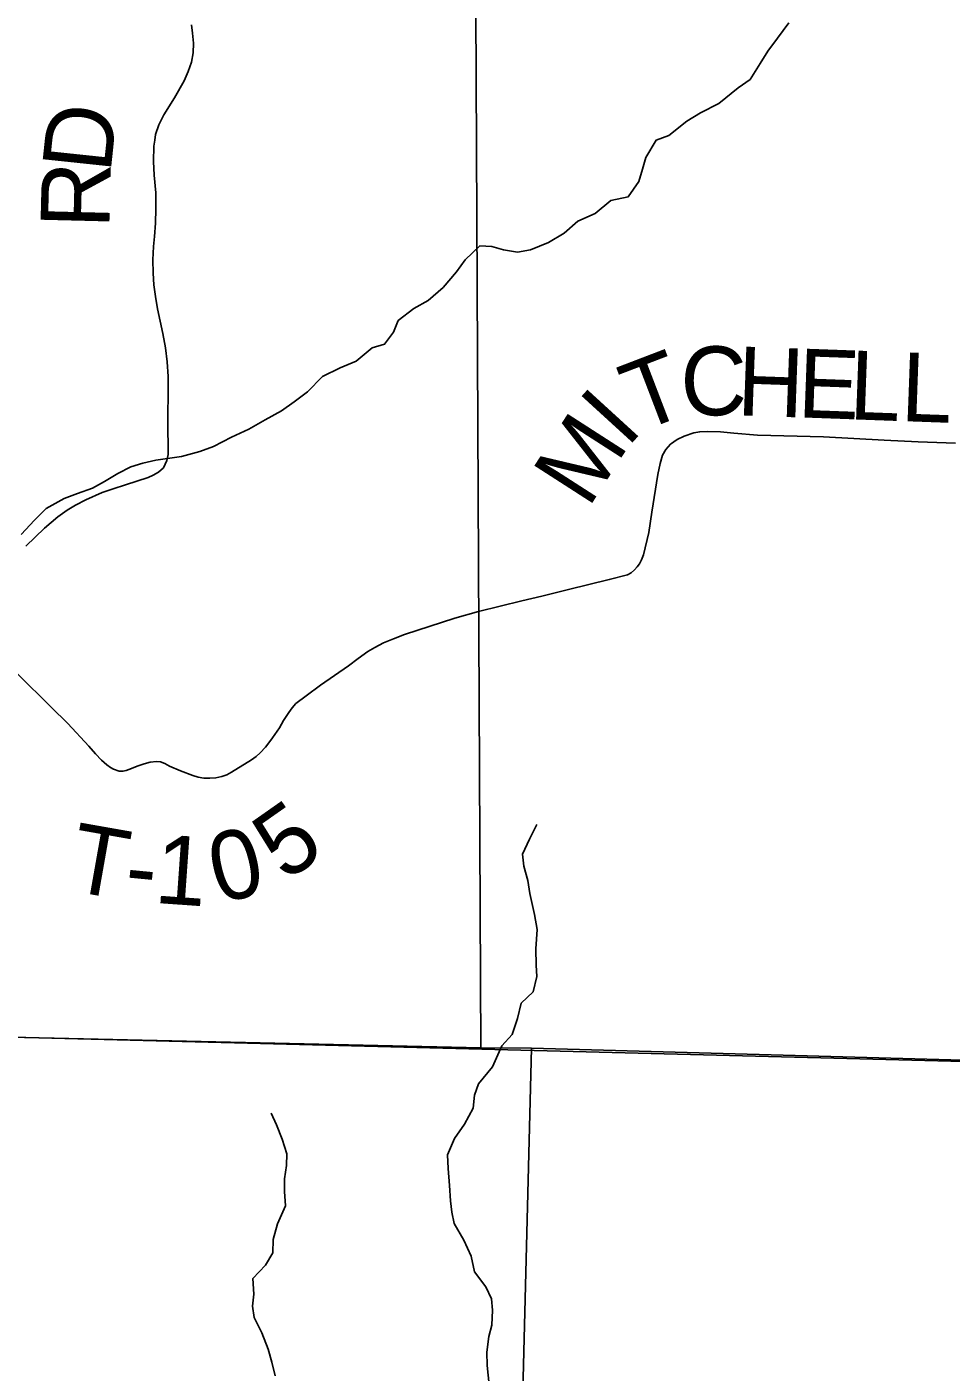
# Model space of a CAD drawing. Extents: x 0 to 34, y 0 to 22.
# Drawn here: x 5.404 to 6.166, y 15.796 to 16.906 of the extents above; entities that cross this region are included whole.
import ezdxf

# ---------------------------------------------------------------- set-up
doc = ezdxf.new("R2010")
doc.units = 0
for name, color, linetype in [('GM_X_Corporation', 7, 'Continuous'), ('GM_X_Minor_River', 7, 'Continuous'), ('GM_X_Township_Road', 7, 'Continuous'), ('GM_X_Township_Road_Text', 7, 'Continuous')]:
    doc.layers.add(name, color=color, linetype=linetype)

msp = doc.modelspace()

# ---------------------------------------------------------------- linework, layer by layer
at = {"layer": 'GM_X_Corporation'}
for points in [[(4.7905, 18.3604), (4.7823, 18.128), (4.7806, 18.0273), (4.765, 16.8754), (4.756, 16.2274), (4.759, 16.0879), (4.9206, 16.0842), (4.928, 16.0841), (4.9731, 16.0831), (4.975, 16.083), (5.0347, 16.0817), (5.0373, 16.0816), (6.4668, 16.045), (6.4721, 16.0449), (6.6873, 16.0404), (6.6909, 16.0403), (6.7034, 16.04), (6.9699, 16.0345), (6.9736, 16.0344), (7.8043, 16.0135), (7.8077, 16.0135), (8.4311, 16.0029), (8.4311, 20.028)], [(6.4668, 16.045), (5.0373, 16.0816)]]:
    msp.add_lwpolyline(points, dxfattribs=at)
for points in [[(6.7684, 17.0582), (6.7585, 16.0372), (5.82, 16.0635), (5.7783, 16.0638), (5.7733, 17.0918)], [(4.7583, 16.0869), (5.7783, 16.0638), (5.82, 16.0635), (5.7937, 15.0184), (4.7356, 15.0283), (4.7361, 15.0901)], [(5.82, 16.0635), (6.7585, 16.0372), (6.8244, 16.0368), (6.804, 15.0104), (5.7937, 15.0184)]]:
    msp.add_lwpolyline(points, close=True, dxfattribs=at)
at = {"layer": 'GM_X_Minor_River'}
for points in [[(5.399, 16.4872), (5.41, 16.499), (5.4198, 16.5085), (5.4345, 16.5169), (5.4455, 16.5208), (5.458, 16.5253), (5.4678, 16.5307), (5.4788, 16.5375), (5.4897, 16.5429), (5.4996, 16.546), (5.5101, 16.5483), (5.5313, 16.5514), (5.5465, 16.5556), (5.5578, 16.5598), (5.5726, 16.5674), (5.5869, 16.5739), (5.6005, 16.5816), (5.6138, 16.5892), (5.6243, 16.5964), (5.6353, 16.6048), (5.6478, 16.6174), (5.6621, 16.6246), (5.6754, 16.63), (5.6886, 16.641), (5.6988, 16.6441), (5.7063, 16.654), (5.7101, 16.6635), (5.7229, 16.6734), (5.7347, 16.6802), (5.7471, 16.6909), (5.7581, 16.7038), (5.7652, 16.7137), (5.7773, 16.7251), (5.7872, 16.7248), (5.797, 16.7218), (5.8084, 16.7199), (5.8193, 16.7219), (5.8341, 16.728), (5.8469, 16.7356), (5.8583, 16.7455), (5.8726, 16.752), (5.8855, 16.7627), (5.8999, 16.7657), (5.9085, 16.7783), (5.9115, 16.7885), (5.9142, 16.798), (5.9228, 16.8124), (5.9334, 16.8163), (5.9481, 16.8281), (5.9595, 16.8349), (5.9746, 16.8426), (5.9905, 16.8555), (6.0003, 16.8624), (6.0086, 16.8757), (6.015, 16.8859), (6.0229, 16.8966), (6.0323, 16.9091)], [(5.785, 15.7857), (5.7835, 15.8016), (5.7831, 15.8126), (5.7849, 15.8255), (5.7872, 15.835), (5.7879, 15.8472), (5.7871, 15.8566), (5.7825, 15.8665), (5.773, 15.8789), (5.7703, 15.8918), (5.7642, 15.9051), (5.7562, 15.9187), (5.7543, 15.9282), (5.7532, 15.9376), (5.7524, 15.9502), (5.7512, 15.9642), (5.7508, 15.9755), (5.7564, 15.9888), (5.7647, 16.0006), (5.7719, 16.0139), (5.773, 16.0245), (5.7763, 16.034), (5.788, 16.0481), (5.7956, 16.0652), (5.8042, 16.0747), (5.8084, 16.088), (5.8114, 16.1005), (5.8215, 16.11), (5.8245, 16.1225), (5.8238, 16.132), (5.8237, 16.1453), (5.8248, 16.1612), (5.8225, 16.1737), (5.8187, 16.1911), (5.8171, 16.2017), (5.8137, 16.2135), (5.8125, 16.2233), (5.8185, 16.2359), (5.8245, 16.248)], [(5.6086, 15.7931), (5.6059, 15.8044), (5.6028, 15.815), (5.5975, 15.8287), (5.5914, 15.8412), (5.5898, 15.8506), (5.591, 15.8605), (5.5902, 15.8734), (5.6007, 15.8844), (5.6067, 15.8947), (5.6071, 15.9057), (5.6105, 15.9186), (5.6172, 15.9334), (5.6164, 15.9451), (5.6164, 15.9557), (5.6179, 15.9667), (5.6182, 15.9762), (5.6144, 15.9883), (5.6098, 16.0001), (5.6053, 16.0099)]]:
    msp.add_lwpolyline(points, dxfattribs=at)
at = {"layer": 'GM_X_Township_Road'}
for points in [[(5.403, 16.4776), (5.4185, 16.4922), (5.4295, 16.5018), (5.437, 16.5072), (5.444, 16.5114), (5.4525, 16.5158), (5.466, 16.5218), (5.475, 16.5249), (5.4853, 16.5281), (5.5039, 16.5342), (5.5081, 16.5361), (5.5124, 16.5385), (5.5165, 16.542), (5.5193, 16.5481), (5.5203, 16.5532), (5.5201, 16.581), (5.5205, 16.6079), (5.5205, 16.6174), (5.5196, 16.6296), (5.5183, 16.6411), (5.5161, 16.653), (5.5116, 16.6732), (5.5098, 16.6835), (5.5086, 16.6931), (5.5079, 16.7026), (5.5078, 16.7138), (5.5083, 16.7246), (5.509, 16.7328), (5.5098, 16.7439), (5.5102, 16.7557), (5.5102, 16.769), (5.5087, 16.7836), (5.5083, 16.7947), (5.5085, 16.8075), (5.5093, 16.8124), (5.51, 16.8171), (5.5128, 16.8251), (5.5169, 16.8333), (5.5257, 16.8474), (5.5335, 16.8614), (5.5368, 16.8691), (5.5396, 16.8768), (5.5411, 16.8845), (5.5412, 16.8923), (5.5404, 16.9006), (5.5397, 16.9076)], [(5.3951, 16.3733), (5.4063, 16.3621), (5.4136, 16.3549), (5.424, 16.3446), (5.4376, 16.3311), (5.455, 16.3126), (5.4605, 16.3063), (5.4655, 16.3009), (5.4697, 16.2971), (5.4727, 16.295), (5.4754, 16.2936), (5.48, 16.292), (5.483, 16.2918), (5.4858, 16.2925), (5.4879, 16.2932), (5.4957, 16.2962), (5.5007, 16.298), (5.5056, 16.2994), (5.5107, 16.3), (5.5141, 16.2996), (5.5176, 16.2981), (5.5215, 16.296), (5.5305, 16.2923), (5.5407, 16.2884), (5.5452, 16.2869), (5.5498, 16.2861), (5.5548, 16.286), (5.5597, 16.2864), (5.5646, 16.2875), (5.5687, 16.2889), (5.5725, 16.291), (5.5892, 16.3012), (5.593, 16.3039), (5.5963, 16.3069), (5.6006, 16.3116), (5.6035, 16.3152), (5.6064, 16.3195), (5.6121, 16.3276), (5.6155, 16.3336), (5.6198, 16.3403), (5.6226, 16.344), (5.6258, 16.3476), (5.6341, 16.3539), (5.6459, 16.3627), (5.669, 16.3788), (5.6772, 16.3848), (5.685, 16.3905), (5.6909, 16.394), (5.6979, 16.3977), (5.7061, 16.4011), (5.7153, 16.4046), (5.7567, 16.4181), (5.7763, 16.4236), (5.8122, 16.4324), (5.8285, 16.4363), (5.8506, 16.4418), (5.8841, 16.4499), (5.8993, 16.4539), (5.9023, 16.4556), (5.9051, 16.4579), (5.9072, 16.4604), (5.9091, 16.463), (5.9108, 16.4662), (5.9125, 16.4704), (5.9168, 16.4888), (5.9193, 16.5056), (5.9241, 16.5366), (5.9261, 16.5457), (5.9282, 16.5525), (5.9307, 16.5573), (5.9348, 16.5616), (5.9403, 16.5654), (5.9459, 16.5682), (5.9538, 16.5709), (5.9588, 16.5719), (5.9648, 16.5721), (5.9759, 16.5717), (5.9868, 16.5708), (6.0065, 16.5691), (6.0609, 16.5676), (6.1109, 16.5648), (6.139, 16.5636), (6.1696, 16.5624)]]:
    msp.add_lwpolyline(points, dxfattribs=at)

# ---------------------------------------------------------------- texts
at = {"layer": 'GM_X_Township_Road_Text'}
for s, rotation, p in [('D', 83.9784, (5.4728, 16.7845)), ('R', 88.5792, (5.4718, 16.7391)), ('T', 20.9403, (5.9086, 16.5711)), ('C', 0.3122, (5.943, 16.5853)), ('H', 357.956, (5.989, 16.5855)), ('E', 357.9168, (6.039, 16.5838)), ('L', 357.9167, (6.0815, 16.5822)), ('L', 357.9124, (6.124, 16.5807)), ('I', 47.573, (5.8986, 16.5578)), ('M', 57.2479, (5.8668, 16.5079)), ('5', 35.045, (5.617, 16.2001)), ('T', 349.9719, (5.4366, 16.1938)), ('0', 13.4942, (5.5619, 16.1824)), ('1', 355.9871, (5.5082, 16.1833)), ('-', 354.5167, (5.4834, 16.1857))]:
    msp.add_text(s, height=0.0568, rotation=rotation, dxfattribs=at).set_placement(p)

doc.saveas('drawing.dxf')
